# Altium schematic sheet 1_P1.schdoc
size 307 x 218 mm; Symbol: Drawing-Symbol_A4; Device: Drawing-Symbol_A4; Company: 嘉立创EDA; Version: V1.0; Page Size: A4; @Project Name: ESP32_C3_RX; @Page Count: 1; @Update Date: 2025-06-23; @Create Date: 2025-06-14; @Schematic Name: Simplest_Schematic; @Page No: 1; @Page Name: P1; @Create Time: 20:50:11; @Update Time: 09:00:37; Width: 1170; Height: 825; Region Start: 1; X Region Count: 6; Y Region Count: 4; Blade Width: 10; Title Block Position: 3; @Board Name: Board1
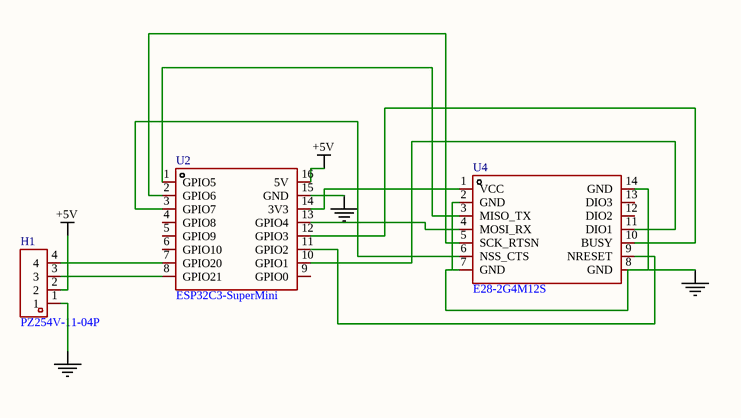
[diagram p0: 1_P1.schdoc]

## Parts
H1  PZ254V-11-04P  [HDR-TH_4P-P2.54-V-M]
U2  ESP32C3-SuperMini  [COMM-SMD_16P-L22.5-W18.0-P2.54-TL]
U4  E28-2G4M12S  [WIRELM-SMD_E28-2G4M12S]

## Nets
+5V: H1.2 U2.16(5V)
GND: H1.1 U2.15(GND) U4.2(GND) U4.7(GND) U4.8(GND) U4.14(GND)
NetH1_3: H1.3 U2.8(GPIO21)
NetH1_4: H1.4 U2.7(GPIO20)
NetU2_1: U2.1(GPIO5) U4.3(MISO_TX)
NetU2_2: U2.2(GPIO6) U4.5(SCK_RTSN)
NetU2_3: U2.3(GPIO7) U2.14(3V3) U4.1(VCC) U4.6(NSS_CTS)
NetU2_10: U2.10(GPIO1) U4.11(DIO1)
NetU2_11: U2.11(GPIO2) U4.9(NRESET)
NetU2_12: U2.12(GPIO3) U4.10(BUSY)
NetU2_13: U2.13(GPIO4) U4.4(MOSI_RX)

Not connected (* = marked no-connect by the designer): U2 4(GPIO8) 5(GPIO9) 6(GPIO10) 9(GPIO0); U4 12(DIO2) 13(DIO3)

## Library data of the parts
H1 = PZ254V-11-04P: Manufacturer: XFCN(兴飞); Symbol: PZ254V-11-04P_C2691448; Add into BOM: yes; Pin Structure: 1x4P; Pitch: 2.54mm; Circluar Pins/Square Pins: 方针; Current Rating (Max): 3A; Voltage Rating (Max): 250V
U2 = ESP32C3-SuperMini: Add into BOM: yes
U4 = E28-2G4M12S: Manufacturer: EBYTE(亿佰特); Add into BOM: yes; Output Power: 12.5dBm; Interface Type: SPI; Modulation System: LoRa；FLRC；GFSK; Voltage - Supply: 1.8V~3.6V; Antenna Type: IPEX接口；板载PCB天线; Receive  Current: 10mA; Send  Current: 45mA; Sensitivity: -129dBm; Communication Distance: 3km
